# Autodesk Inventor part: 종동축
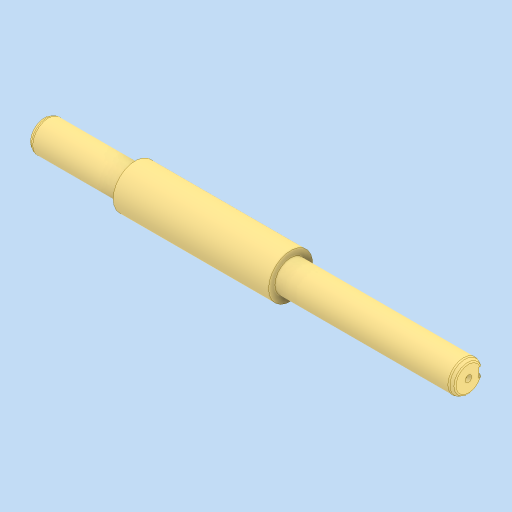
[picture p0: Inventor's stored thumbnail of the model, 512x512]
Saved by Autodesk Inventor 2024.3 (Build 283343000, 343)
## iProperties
Created: 2026-01
Part Number: 종동축
Material: 강철, 탄소
Document SubType Name: Modeling
Designer: PC2-02
Density: 7.85 g/cm^3
Appearance: 기본값
Author: jhkim
Sending System: Autodesk Inventor 2026
Preprocessor: ST-DEVELOPER v20.1
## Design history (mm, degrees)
node "종동축1"
node "솔리드2"
node "솔리드1"
